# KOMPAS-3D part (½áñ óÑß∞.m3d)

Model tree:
1. Эскиз:1
2. Операция выдавливания:1
     Расстояние 1 = 20
3. Эскиз:2
4. Операция выдавливания:2
     Расстояние 1 = 400
5. Эскиз:3
6. Вырезать элемент выдавливания:1
     Расстояние 1 = 70
7. Эскиз:4
8. Вырезать элемент выдавливания:2
     Расстояние 1 = 2
9. Эскиз:5
10. Эскиз:11
11. Вырезать элемент выдавливания:7
     Расстояние 1 = 30
12. Операция выдавливания:3
     Расстояние 1 = 16.96
13. Эскиз:13
14. Вырезать элемент выдавливания:9
     Расстояние 1 = 70
